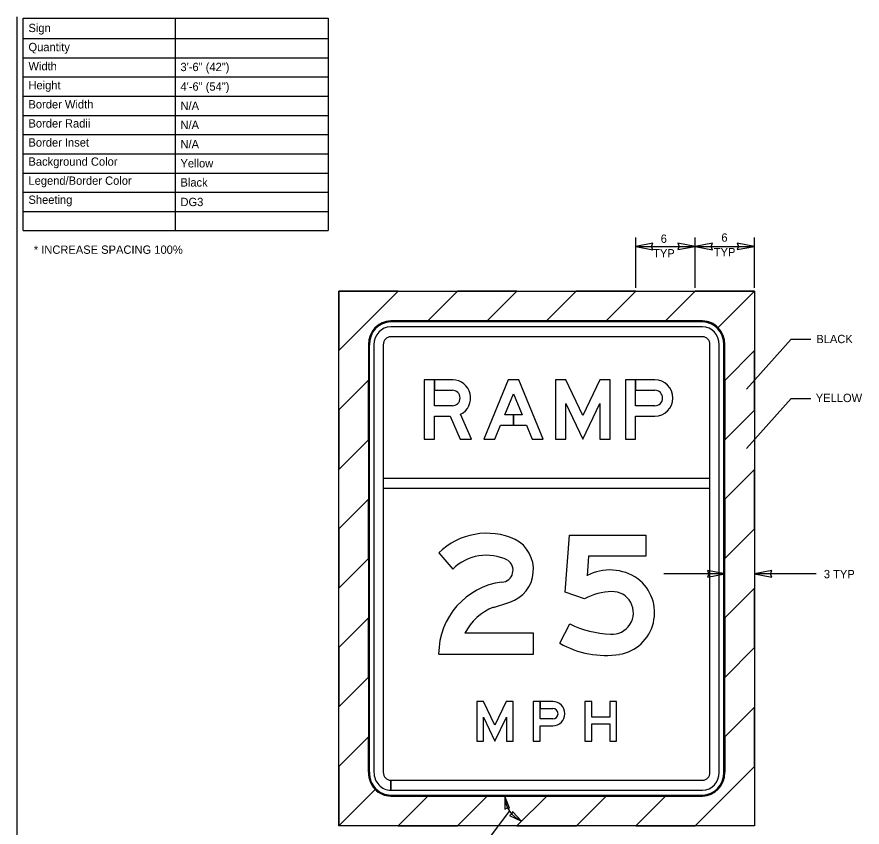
# Model space of a CAD drawing. Extents: x 582908 to 586040, y 1530940 to 1533040.
# Drawn here: x 584558 to 585981, y 1531676 to 1533040 of the extents above; entities that cross this region are included whole.
import ezdxf

# ---------------------------------------------------------------- set-up
doc = ezdxf.new("R2010")
doc.units = 0
for name, color, linetype in [('GSDims', 7, 'Continuous'), ('SheetLinesMisc2_dp', 7, 'Continuous'), ('SignPanel', 7, 'Continuous'), ('TextMisc', 7, 'Continuous'), ('TextNotes', 7, 'Continuous'), ('TextShtNo', 7, 'Continuous')]:
    doc.layers.add(name, color=color, linetype=linetype)

msp = doc.modelspace()

# ---------------------------------------------------------------- linework, layer by layer
at = {"layer": 'GSDims'}
for p, q in [((585600.1, 1532583.6), (585600.1, 1532668.3)), ((585700.1, 1532583.6), (585700.1, 1532668.3)), ((585800.1, 1532583.6), (585800.1, 1532668.3)), ((585629.1, 1532658.7), (585600.1, 1532653.3)), ((585600.1, 1532653.3), (585700.1, 1532653.3)), ((585600.1, 1532653.3), (585629.1, 1532647.7)), ((585626.9, 1532653.3), (585629.1, 1532658.7)), ((585629.1, 1532647.7), (585626.9, 1532653.3)), ((585700.1, 1532653.3), (585671.1, 1532658.9)), ((585671.1, 1532658.9), (585673.3, 1532653.3)), ((585673.3, 1532653.3), (585671.1, 1532647.9)), ((585671.1, 1532647.9), (585700.1, 1532653.3)), ((585729.1, 1532658.7), (585700.1, 1532653.3)), ((585700.1, 1532653.3), (585800.1, 1532653.3)), ((585700.1, 1532653.3), (585729.1, 1532647.7)), ((585726.9, 1532653.3), (585729.1, 1532658.7)), ((585729.1, 1532647.7), (585726.9, 1532653.3)), ((585800.1, 1532653.3), (585771.1, 1532658.9)), ((585771.1, 1532658.9), (585773.3, 1532653.3)), ((585773.3, 1532653.3), (585771.1, 1532647.9)), ((585771.1, 1532647.9), (585800.1, 1532653.3)), ((585786.8, 1532413), (585861.9, 1532497.4)), ((585861.9, 1532497.4), (585895, 1532497.4)), ((585786.8, 1532313), (585861.9, 1532397.4)), ((585861.9, 1532397.4), (585895, 1532397.4)), ((585750.1, 1532102.1), (585647.3, 1532102.1)), ((585750.1, 1532102.1), (585721.1, 1532107.7)), ((585721.1, 1532107.7), (585723.3, 1532102.1)), ((585723.3, 1532102.1), (585721.1, 1532096.7)), ((585721.1, 1532096.7), (585750.1, 1532102.1)), ((585829.1, 1532107.5), (585800.1, 1532102.1)), ((585904.1, 1532102.1), (585800.1, 1532102.1)), ((585800.1, 1532102.1), (585829.1, 1532096.5)), ((585826.9, 1532102.1), (585829.1, 1532107.5)), ((585829.1, 1532096.5), (585826.9, 1532102.1)), ((585380, 1531728.1), (585379.8, 1531705.9)), ((585387.9, 1531707.4), (585380, 1531728.1)), ((585346, 1531647.2), (585387.6, 1531702.7)), ((585379.8, 1531705.9), (585383.6, 1531708.3)), ((585383.6, 1531708.3), (585387.9, 1531707.4)), ((585391.6, 1531697.6), (585387.9, 1531695.3)), ((585392.7, 1531702), (585391.6, 1531697.6)), ((585407.9, 1531685.9), (585392.7, 1531702)), ((585387.9, 1531695.3), (585407.9, 1531685.9))]:
    msp.add_line(p, q, dxfattribs=at)
msp.add_arc((585424.4, 1531727.2), 44.2, 178.9271, 248.409, dxfattribs=at)
at = {"layer": 'SheetLinesMisc2_dp'}
for p, q in [((584558.3, 1533039.8), (584558.3, 1531119.8)), ((584569, 1532679.9), (584569, 1533037.8)), ((584569, 1533037.8), (585082.3, 1533037.8)), ((584824.9, 1533037.8), (584824.9, 1532679.9)), ((585082.3, 1533037.8), (585082.3, 1532679.9)), ((584569, 1533003.3), (585082.3, 1533003.3)), ((584569, 1532970.9), (585082.3, 1532970.9)), ((584569, 1532938.6), (585082.3, 1532938.6)), ((584569, 1532906.2), (585082.3, 1532906.2)), ((584569, 1532873.9), (585082.3, 1532873.9)), ((584569, 1532841.6), (585082.3, 1532841.6)), ((584569, 1532809.2), (585082.3, 1532809.2)), ((584569, 1532776.9), (585082.3, 1532776.9)), ((584569, 1532744.5), (585082.3, 1532744.5)), ((584569, 1532712.2), (585082.3, 1532712.2)), ((584569, 1532679.9), (585082.3, 1532679.9))]:
    msp.add_line(p, q, dxfattribs=at)
at = {"layer": 'SignPanel'}
for p, q in [((585200.1, 1532577.9), (585100.1, 1532577.9)), ((585712.6, 1532527.9), (585187.6, 1532527.9)), ((585187.6, 1532526.3), (585187.6, 1532526.3)), ((585712.6, 1532526.3), (585187.6, 1532526.3)), ((585712.6, 1532526.3), (585712.6, 1532526.3)), ((585712.6, 1532517.9), (585187.6, 1532517.9)), ((585712.6, 1532501.3), (585187.6, 1532501.3)), ((585150.1, 1532487.9), (585150.1, 1531768)), ((585150.1, 1532487.9), (585150.1, 1531768)), ((585151.6, 1532487.9), (585151.6, 1531768)), ((585151.6, 1532487.9), (585151.7, 1532487.9)), ((585159.5, 1532487.9), (585159.5, 1531768)), ((585175.1, 1532487.9), (585175.1, 1531768)), ((585725.1, 1531768), (585725.1, 1532487.9)), ((585740.7, 1531768), (585740.7, 1532487.9)), ((585748.5, 1532487.9), (585748.5, 1532487.9)), ((585748.5, 1531768), (585748.5, 1532487.9)), ((585750.1, 1531768), (585750.1, 1532487.9)), ((585291.4, 1532385.1), (585261.1, 1532385.1)), ((585632.5, 1532385), (585600, 1532385)), ((585600, 1532367.5), (585632.4, 1532367.5)), ((585725.1, 1532262.9), (585175.1, 1532262.9)), ((585175.1, 1532262.9), (585175.1, 1532246.3)), ((585725.1, 1532262.9), (585175.1, 1532262.9)), ((585175.1, 1532262.9), (585175.1, 1532246.3)), ((585725.1, 1532262.9), (585175.1, 1532262.9)), ((585175.1, 1532262.9), (585175.1, 1532246.3)), ((585725.1, 1532246.3), (585725.1, 1532262.9)), ((585725.1, 1532246.3), (585725.1, 1532262.9)), ((585725.1, 1532246.3), (585725.1, 1532262.9)), ((585175.1, 1532246.3), (585725.1, 1532246.3)), ((585175.1, 1532246.3), (585725.1, 1532246.3)), ((585175.1, 1532246.3), (585725.1, 1532246.3)), ((585268.4, 1532137.3), (585292.1, 1532110)), ((585268.4, 1532137.3), (585292.1, 1532110)), ((585268.4, 1532137.3), (585292.1, 1532110)), ((585518.1, 1532099), (585518.1, 1532099)), ((585472.2, 1531985.5), (585489.1, 1532017.8)), ((585472.2, 1531985.5), (585489.1, 1532017.8)), ((585472.2, 1531985.5), (585489.1, 1532017.8)), ((585489.1, 1532017.8), (585489.1, 1532017.8)), ((585489.1, 1532017.8), (585489.1, 1532017.8)), ((585460.7, 1531858), (585439.1, 1531858)), ((585439.1, 1531846.3), (585460.7, 1531846.3)), ((585151.7, 1531768), (585151.6, 1531768)), ((585748.5, 1531768), (585748.5, 1531768)), ((585187.6, 1531738), (585187.6, 1531754.7)), ((585187.7, 1531754.7), (585712.6, 1531754.7)), ((585187.7, 1531754.7), (585187.7, 1531738)), ((585187.6, 1531728), (585187.6, 1531729.7)), ((585187.6, 1531729.7), (585187.6, 1531729.7)), ((585187.6, 1531729.7), (585712.6, 1531729.7)), ((585187.6, 1531729.7), (585187.6, 1531728)), ((585187.6, 1531728), (585712.6, 1531728)), ((585187.7, 1531738), (585712.6, 1531738)), ((585712.6, 1531729.7), (585712.6, 1531729.7))]:
    msp.add_line(p, q, dxfattribs=at)
for points in [[(585200.1, 1532577.9), (585100.1, 1532577.9), (585100.1, 1532478), (585200.1, 1532577.9)], [(585250.1, 1532527.9), (585350.1, 1532527.9), (585400.1, 1532577.9), (585300.1, 1532577.9), (585250.1, 1532527.9)], [(585450.1, 1532527.9), (585550.1, 1532527.9), (585600.1, 1532577.9), (585500.1, 1532577.9), (585450.1, 1532527.9)], [(585738.7, 1532516.6), (585800.1, 1532577.9), (585700.1, 1532577.9), (585650.1, 1532527.9), (585712.6, 1532527.9)], [(585750.1, 1532427.9), (585750.1, 1532327.9), (585800.1, 1532377.9), (585800.1, 1532477.9), (585750.1, 1532427.9)], [(585100.1, 1532378), (585100.1, 1532278), (585150.1, 1532328), (585150.1, 1532428), (585100.1, 1532378)], [(585292, 1532428.8), (585243.8, 1532428.8), (585243.8, 1532328.8), (585261.1, 1532328.8), (585261.1, 1532367.6), (585287.6, 1532367.6)], [(585291.4, 1532385.1), (585261.1, 1532385.1), (585261.1, 1532428.8), (585243.8, 1532428.8), (585243.8, 1532328.8)], [(585291.4, 1532385.1), (585261.1, 1532385.1), (585261.1, 1532428.8), (585243.8, 1532428.8), (585243.8, 1532328.8)], [(585292, 1532428.8), (585261.1, 1532428.8), (585261.1, 1532411.3), (585291.4, 1532411.3)], [(585292, 1532428.8), (585261.1, 1532428.8), (585261.1, 1532411.3), (585291.4, 1532411.3)], [(585632.4, 1532428.8), (585582.8, 1532428.8), (585582.8, 1532328.8), (585600, 1532328.8), (585600, 1532367.5)], [(585600, 1532428.8), (585582.8, 1532428.8), (585582.8, 1532328.8), (585600, 1532328.8), (585600, 1532367.5), (585632.4, 1532367.5)], [(585600, 1532428.8), (585582.8, 1532428.8), (585582.8, 1532328.8), (585600, 1532328.8), (585600, 1532367.5), (585632.4, 1532367.5)], [(585632.4, 1532428.8), (585600, 1532428.8), (585600, 1532411.3), (585632.5, 1532411.3)], [(585632.5, 1532385), (585600, 1532385), (585600, 1532428.8)], [(585632.4, 1532428.8), (585600, 1532428.8), (585600, 1532411.3), (585632.5, 1532411.3)], [(585632.5, 1532385), (585600, 1532385), (585600, 1532428.8)], [(585261.1, 1532385.1), (585261.1, 1532411.3), (585291.4, 1532411.3)], [(585600, 1532385), (585600, 1532411.3), (585632.5, 1532411.3)], [(585243.8, 1532328.8), (585261.1, 1532328.8), (585261.1, 1532367.6), (585287.6, 1532367.6), (585304.7, 1532328.8), (585323.6, 1532328.8), (585305.2, 1532370.7)], [(585243.8, 1532328.8), (585261.1, 1532328.8), (585261.1, 1532367.6), (585287.6, 1532367.6), (585304.7, 1532328.8), (585323.6, 1532328.8), (585305.2, 1532370.7)], [(585287.6, 1532367.6), (585304.7, 1532328.8), (585323.6, 1532328.8), (585305.2, 1532370.7)], [(585750.1, 1532127.9), (585800.1, 1532177.9), (585800.1, 1532277.9), (585750.1, 1532227.9), (585750.1, 1532127.9)], [(585150.1, 1532128), (585150.1, 1532228), (585100.1, 1532178), (585100.1, 1532078), (585150.1, 1532128)], [(585514, 1532060.3), (585481.5, 1532071.2), (585488.6, 1532167.1), (585616.9, 1532167.1), (585616.9, 1532132.1), (585520.6, 1532132.1), (585518.1, 1532099)], [(585514, 1532060.3), (585481.5, 1532071.2), (585488.6, 1532167.1), (585616.9, 1532167.1), (585616.9, 1532132.1), (585520.6, 1532132.1), (585518.1, 1532099)], [(585514, 1532060.3), (585481.5, 1532071.2), (585488.6, 1532167.1), (585616.9, 1532167.1), (585616.9, 1532132.1), (585520.6, 1532132.1), (585518.1, 1532099)], [(585750.1, 1531927.9), (585800.1, 1531977.9), (585800.1, 1532077.9), (585750.1, 1532027.9), (585750.1, 1531927.9)], [(585150.1, 1531928), (585150.1, 1532028), (585100.1, 1531978), (585100.1, 1531878), (585150.1, 1531928)], [(585268.4, 1531967.1), (585427.9, 1531967.1), (585427.9, 1532002.1), (585312.6, 1532002.1)], [(585268.4, 1531967.1), (585427.9, 1531967.1), (585427.9, 1532002.1), (585312.6, 1532002.1)], [(585268.4, 1531967.1), (585427.9, 1531967.1), (585427.9, 1532002.1), (585312.6, 1532002.1)], [(585460.7, 1531887.2), (585427.6, 1531887.2), (585427.6, 1531820.5), (585439.1, 1531820.5), (585439.1, 1531846.3)], [(585439.1, 1531887.2), (585427.6, 1531887.2), (585427.6, 1531820.5), (585439.1, 1531820.5), (585439.1, 1531846.3), (585460.7, 1531846.3)], [(585439.1, 1531887.2), (585427.6, 1531887.2), (585427.6, 1531820.5), (585439.1, 1531820.5), (585439.1, 1531846.3), (585460.7, 1531846.3)], [(585460.7, 1531887.2), (585439.1, 1531887.2), (585439.1, 1531875.5), (585460.7, 1531875.5)], [(585460.7, 1531858), (585439.1, 1531858), (585439.1, 1531887.2)], [(585460.7, 1531887.2), (585439.1, 1531887.2), (585439.1, 1531875.5), (585460.7, 1531875.5)], [(585460.7, 1531858), (585439.1, 1531858), (585439.1, 1531887.2)], [(585439.1, 1531858), (585439.1, 1531875.5), (585460.7, 1531875.5)], [(585712.6, 1531728), (585650.2, 1531728), (585600.2, 1531678), (585700.2, 1531678), (585800.1, 1531777.9), (585800.1, 1531877.9), (585750.1, 1531827.9)], [(585150.1, 1531768), (585150.1, 1531828), (585100.1, 1531778), (585100.1, 1531678), (585161.5, 1531739.3)], [(585750.1, 1531827.9), (585750.1, 1531768)], [(585300.2, 1531678), (585350.2, 1531728), (585250.2, 1531728), (585200.2, 1531678), (585300.2, 1531678)], [(585500.2, 1531678), (585550.2, 1531728), (585450.2, 1531728), (585400.2, 1531678), (585500.2, 1531678)]]:
    msp.add_lwpolyline(points, dxfattribs=at)
for points in [[(585100.1, 1532577.9), (585800.1, 1532577.9), (585800.1, 1531678), (585100.1, 1531678)], [(585416, 1532352.3), (585425.7, 1532328.8), (585444.3, 1532328.8), (585403.4, 1532428.8), (585385.2, 1532428.8), (585344.3, 1532328.8), (585363, 1532328.8), (585372.7, 1532352.3)], [(585372.7, 1532352.3), (585394.3, 1532352.3), (585394.3, 1532369.8), (585379.8, 1532369.8), (585394.3, 1532405.3), (585408.9, 1532369.8), (585394.3, 1532369.8), (585394.3, 1532352.3), (585416, 1532352.3), (585425.7, 1532328.8), (585444.3, 1532328.8), (585403.4, 1532428.8), (585385.2, 1532428.8), (585344.3, 1532328.8), (585363, 1532328.8)], [(585372.7, 1532352.3), (585394.3, 1532352.3), (585394.3, 1532369.8), (585379.8, 1532369.8), (585394.3, 1532405.3), (585408.9, 1532369.8), (585394.3, 1532369.8), (585394.3, 1532352.3), (585416, 1532352.3), (585425.7, 1532328.8), (585444.3, 1532328.8), (585403.4, 1532428.8), (585385.2, 1532428.8), (585344.3, 1532328.8), (585363, 1532328.8)], [(585482.3, 1532389), (585511.1, 1532328.8), (585539.9, 1532389), (585539.9, 1532328.8), (585557.1, 1532328.8), (585557.1, 1532428.8), (585539.8, 1532428.8), (585511.1, 1532368.8), (585482.4, 1532428.8), (585465, 1532428.8), (585465, 1532328.8), (585482.3, 1532328.8)], [(585482.3, 1532389), (585511.1, 1532328.8), (585539.9, 1532389), (585539.9, 1532328.8), (585557.1, 1532328.8), (585557.1, 1532428.8), (585539.8, 1532428.8), (585511.1, 1532368.8), (585482.4, 1532428.8), (585465, 1532428.8), (585465, 1532328.8), (585482.3, 1532328.8)], [(585482.3, 1532389), (585511.1, 1532328.8), (585539.9, 1532389), (585539.9, 1532328.8), (585557.1, 1532328.8), (585557.1, 1532428.8), (585539.8, 1532428.8), (585511.1, 1532368.8), (585482.4, 1532428.8), (585465, 1532428.8), (585465, 1532328.8), (585482.3, 1532328.8)], [(585394.3, 1532405.3), (585408.9, 1532369.8), (585379.8, 1532369.8)], [(585343.9, 1531860.7), (585363.1, 1531820.5), (585382.3, 1531860.7), (585382.3, 1531820.5), (585393.8, 1531820.5), (585393.8, 1531887.2), (585382.2, 1531887.2), (585363.1, 1531847.2), (585344, 1531887.2), (585332.4, 1531887.2), (585332.4, 1531820.5), (585343.9, 1531820.5)], [(585343.9, 1531860.7), (585363.1, 1531820.5), (585382.3, 1531860.7), (585382.3, 1531820.5), (585393.8, 1531820.5), (585393.8, 1531887.2), (585382.2, 1531887.2), (585363.1, 1531847.2), (585344, 1531887.2), (585332.4, 1531887.2), (585332.4, 1531820.5), (585343.9, 1531820.5)], [(585343.9, 1531860.7), (585363.1, 1531820.5), (585382.3, 1531860.7), (585382.3, 1531820.5), (585393.8, 1531820.5), (585393.8, 1531887.2), (585382.2, 1531887.2), (585363.1, 1531847.2), (585344, 1531887.2), (585332.4, 1531887.2), (585332.4, 1531820.5), (585343.9, 1531820.5)], [(585556.3, 1531861.1), (585526.1, 1531861.1), (585526.1, 1531887.2), (585514.6, 1531887.2), (585514.6, 1531820.5), (585526.1, 1531820.5), (585526.1, 1531849.4), (585556.3, 1531849.4), (585556.3, 1531820.5), (585567.8, 1531820.5), (585567.8, 1531887.2), (585556.3, 1531887.2)], [(585556.3, 1531861.1), (585526.1, 1531861.1), (585526.1, 1531887.2), (585514.6, 1531887.2), (585514.6, 1531820.5), (585526.1, 1531820.5), (585526.1, 1531849.4), (585556.3, 1531849.4), (585556.3, 1531820.5), (585567.8, 1531820.5), (585567.8, 1531887.2), (585556.3, 1531887.2)], [(585556.3, 1531861.1), (585526.1, 1531861.1), (585526.1, 1531887.2), (585514.6, 1531887.2), (585514.6, 1531820.5), (585526.1, 1531820.5), (585526.1, 1531849.4), (585556.3, 1531849.4), (585556.3, 1531820.5), (585567.8, 1531820.5), (585567.8, 1531887.2), (585556.3, 1531887.2)]]:
    msp.add_lwpolyline(points, close=True, dxfattribs=at)
for centre, major_axis, ratio, start_param, end_param in [((585187.6, 1532487.9), (0, 40), 0.937555, 0, 1.570796), ((585187.6, 1532487.9), (0, 40), 0.937555, 0, 1.570796), ((585187.6, 1532487.9), (0, 38.3), 0.937555, 0, 1.570796), ((585712.6, 1532487.9), (0, 40), 0.937555, 4.712389, 6.283185), ((585712.6, 1532487.9), (0, 40), 0.937555, 5.51114, 6.283185), ((585712.6, 1532487.9), (0, 40), 0.937555, 4.712389, 6.283185), ((585712.6, 1532487.9), (0, 38.3), 0.937555, 4.712389, 6.283185), ((585187.6, 1532487.9), (0, 30), 0.937555, 0, 1.570796), ((585712.6, 1532487.9), (0, 30), 0.937555, 4.712389, 6.283185), ((585187.6, 1532487.9), (0, 13.3), 0.937555, 0, 1.570796), ((585712.6, 1532487.9), (0, 13.3), 0.937555, 4.712389, 6.283185), ((585292, 1532398.2), (0, 30.6), 0.985, 3.595687, 6.283185), ((585292, 1532398.2), (0, 30.6), 0.985, 3.595687, 6.283185), ((585292, 1532398.2), (0, 30.6), 0.985, 3.595687, 6.283185), ((585632.4, 1532398.1), (0, 30.6), 0.985, 3.141593, 6.283185), ((585632.4, 1532398.1), (0, 30.6), 0.985, 3.141593, 6.283185), ((585632.4, 1532398.1), (0, 30.6), 0.985, 3.141593, 6.283185), ((585291.4, 1532398.2), (0, 13.1), 0.985, 3.141593, 6.283185), ((585291.4, 1532398.2), (0, 13.1), 0.985, 3.141593, 6.283185), ((585291.4, 1532398.2), (0, 13.1), 0.985, 3.141593, 6.283185), ((585632.5, 1532398.1), (0, 13.1), 0.985, 3.141593, 6.283185), ((585632.5, 1532398.1), (0, 13.1), 0.985, 3.141593, 6.283185), ((585632.5, 1532398.1), (0, 13.1), 0.985, 3.141593, 6.283185), ((585349.5, 1532051.6), (0, 118.8), 0.985, 5.861869, 7.048709), ((585349.5, 1532051.6), (0, 118.8), 0.985, 5.861869, 7.048709), ((585349.5, 1532051.6), (0, 118.8), 0.985, 5.861869, 7.048709), ((585371.6, 1532109.2), (0, 57.2), 0.985, 3.445077, 5.80948), ((585371.6, 1532109.2), (0, 57.2), 0.985, 3.445077, 5.80948), ((585371.6, 1532109.2), (0, 57.2), 0.985, 3.445077, 5.80948), ((585349, 1532050.4), (0, 83), 0.985, 5.833638, 7.052577), ((585349, 1532050.4), (0, 83), 0.985, 5.833638, 7.052577), ((585349, 1532050.4), (0, 83), 0.985, 5.833638, 7.052577), ((585373.8, 1532108.2), (0, 20.1), 0.985, 3.193411, 5.709913), ((585373.8, 1532108.2), (0, 20.1), 0.985, 3.193411, 5.709913), ((585373.8, 1532108.2), (0, 20.1), 0.985, 3.193411, 5.709913), ((585556.5, 1532025.1), (0, 83.6), 0.985, 5.674797, 6.76791), ((585556.5, 1532025.1), (0, 83.6), 0.985, 5.674797, 6.76791), ((585556.5, 1532025.1), (0, 83.6), 0.985, 5.674797, 6.76791), ((585389.5, 1531966.1), (0, 123), 0.985, 0.121378, 1.562513), ((585389.5, 1531966.1), (0, 123), 0.985, 0.121378, 1.562513), ((585389.5, 1531966.1), (0, 123), 0.985, 0.121378, 1.562513), ((585562, 1532036.7), (0, 70.9), 0.985, 3.29706, 5.646286), ((585562, 1532036.7), (0, 70.9), 0.985, 3.29706, 5.646286), ((585562, 1532036.7), (0, 70.9), 0.985, 3.29706, 5.646286), ((585562.1, 1531967.1), (0, 105.2), 0.985, 0.021733, 0.482857), ((585562.1, 1531967.1), (0, 105.2), 0.985, 0.021733, 0.482857), ((585562.1, 1531967.1), (0, 105.2), 0.985, 0.021733, 0.482857), ((585560.8, 1532036.4), (0, 35.9), 0.985, 3.050128, 6.31212), ((585560.8, 1532036.4), (0, 35.9), 0.985, 3.050128, 6.31212), ((585560.8, 1532036.4), (0, 35.9), 0.985, 3.050128, 6.31212), ((585179.7, 1532679.5), (0, 659.8), 0.985, 3.423454, 3.46857), ((585179.7, 1532679.5), (0, 659.8), 0.985, 3.423454, 3.46857), ((585179.7, 1532679.5), (0, 659.8), 0.985, 3.423454, 3.46857), ((585391.2, 1531962.1), (0, 89.3), 0.985, 0.357174, 1.105945), ((585391.2, 1531962.1), (0, 89.3), 0.985, 0.357174, 1.105945), ((585391.2, 1531962.1), (0, 89.3), 0.985, 0.357174, 1.105945), ((585564.8, 1532180), (0, 179.5), 0.985, 2.699218, 3.100889), ((585564.8, 1532180), (0, 179.5), 0.985, 2.699218, 3.100889), ((585564.8, 1532180), (0, 179.5), 0.985, 2.699218, 3.100889), ((585549.4, 1532123.6), (0, 158.8), 0.985, 2.625811, 3.292278), ((585549.4, 1532123.6), (0, 158.8), 0.985, 2.625811, 3.292278), ((585549.4, 1532123.6), (0, 158.8), 0.985, 2.625811, 3.292278), ((585460.7, 1531866.7), (0, 20.4), 0.985, 3.141593, 6.283185), ((585460.7, 1531866.7), (0, 20.4), 0.985, 3.141593, 6.283185), ((585460.7, 1531866.7), (0, 20.4), 0.985, 3.141593, 6.283185), ((585460.7, 1531866.7), (0, 8.75), 0.985, 3.141593, 6.283185), ((585460.7, 1531866.7), (0, 8.75), 0.985, 3.141593, 6.283185), ((585460.7, 1531866.7), (0, 8.75), 0.985, 3.141593, 6.283185), ((585187.6, 1531768), (0, 40), 0.937555, 1.570796, 2.370551), ((585187.6, 1531768), (0, 40), 0.937555, 1.570796, 3.141593), ((585187.6, 1531768), (0, 38.3), 0.937555, 1.570796, 3.141593), ((585187.6, 1531768), (0, 30), 0.937555, 1.570796, 3.141593), ((585187.6, 1531768), (0, 13.3), 0.937555, 1.570796, 3.141593), ((585712.6, 1531768), (0, 40), 0.937555, 3.141593, 4.712389), ((585712.6, 1531768), (0, 40), 0.937555, 3.141593, 4.712389), ((585712.6, 1531768), (0, 30), 0.937555, 3.141593, 4.712389), ((585712.6, 1531768), (0, 13.3), 0.937555, 3.141593, 4.712389), ((585712.6, 1531768), (0, 40), 0.937555, 3.141593, 4.712389), ((585712.6, 1531768), (0, 38.3), 0.937555, 3.141593, 4.712389)]:
    msp.add_ellipse(centre, major_axis=major_axis, ratio=ratio, start_param=start_param, end_param=end_param, dxfattribs=at)

# ---------------------------------------------------------------- texts
at = {"layer": 'GSDims'}
for s, p in [('6', (585642.2, 1532659.3)), ('6', (585744.3, 1532661.3)), ('TYP', (585731.5, 1532636.8)), ('TYP', (585629.4, 1532634.8)), ('BLACK', (585904.1, 1532490.5)), ('YELLOW', (585903.2, 1532391.3)), ('3 TYP', (585916.8, 1532094.7))]:
    msp.add_text(s, height=14, dxfattribs=at).set_placement(p)
at = {"layer": 'TextMisc'}
for s, p in [('Sign', (584577.8, 1533014.2)), ('Quantity', (584577.8, 1532982)), ('Width', (584577.8, 1532949.9)), ('Height', (584577.8, 1532917.8)), ('Border Width', (584577.8, 1532885.6)), ('Border Radii', (584577.8, 1532853.5)), ('Border Inset', (584577.8, 1532821.4)), ('Background Color', (584577.8, 1532789.2)), ('Legend/Border Color', (584577.8, 1532757.1)), ('Sheeting', (584577.8, 1532725))]:
    msp.add_text(s, height=14, dxfattribs=at).set_placement(p)
at = {"layer": 'TextNotes'}
msp.add_text('* INCREASE SPACING 100%', height=14, dxfattribs=at).set_placement((584586.8, 1532640.9))
at = {"layer": 'TextShtNo'}
for s, p in [('3\'-6" (42")', (584833.7, 1532948.5)), ('4\'-6" (54")', (584833.7, 1532915.6)), ('N/A', (584833.7, 1532883.2)), ('N/A', (584833.7, 1532850.9)), ('N/A', (584833.7, 1532818.6)), ('Yellow', (584833.7, 1532786.3)), ('Black', (584833.7, 1532754.1)), ('DG3', (584833.7, 1532721.2))]:
    msp.add_text(s, height=14, dxfattribs=at).set_placement(p)

doc.saveas('drawing.dxf')
